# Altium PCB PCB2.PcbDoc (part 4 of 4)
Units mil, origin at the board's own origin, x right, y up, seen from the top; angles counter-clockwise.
Board outline 3980.79 x 2126 mil, 6 copper layers (Top Layer, Signal Layer 1, Signal Layer 2, Signal Layer 3, Signal Layer 4, Bottom Layer), stack 61.485 mil thick; 358 components, 190 nets, 1000 pads, 509 vias.
Unrouted connection lines stored in the file: 83.
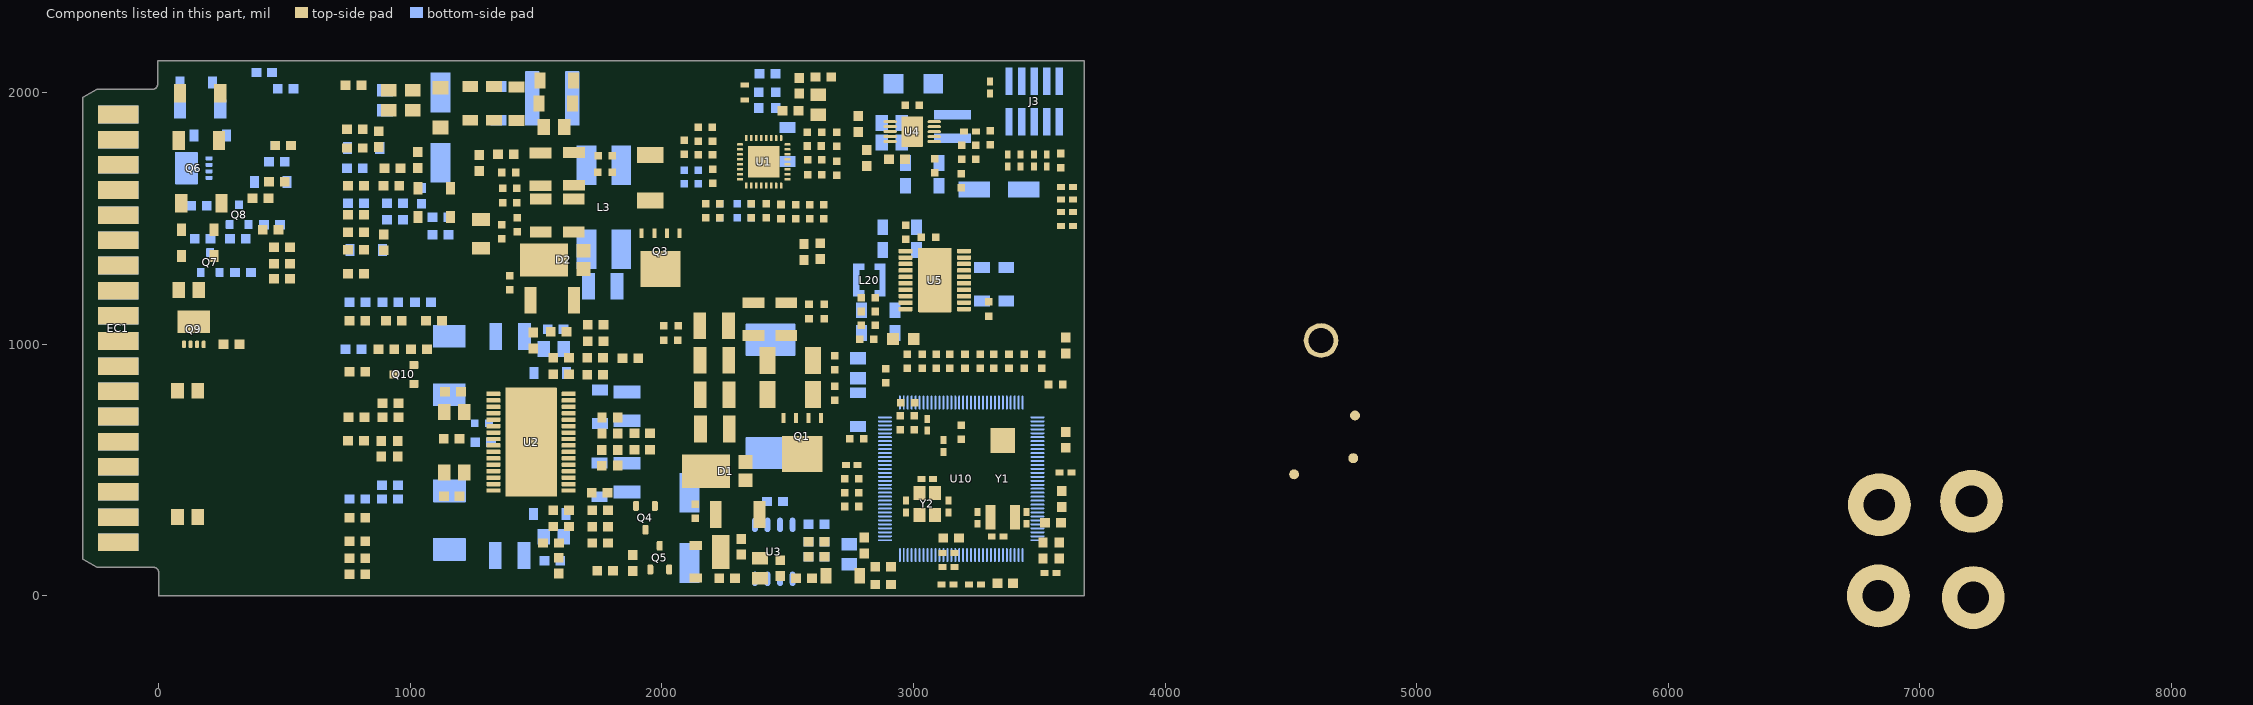
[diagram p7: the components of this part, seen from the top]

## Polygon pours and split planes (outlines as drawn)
Vin on Bottom Layer "BOTTOM_LAYER_VIN_P214" (solid, remove dead copper, pour order 214): 1575,2100.5 1575,1775 1765,1775 1770,1780 1770,2100.5
3V3 on Bottom Layer "BOTTOM_LAYER_3V3_P198" (solid, remove dead copper, pour order 198): 2740,1005 2740,1330 2815,1330 2815,1005
NetC68_1 on Bottom Layer "BOTTOM_LAYER_NETC68_1_P126" (solid, remove dead copper, pour order 126): 850,2100 850,1975 1350,1975 1455,1870 1515,1870 1515,2100
NetC68_1 on Bottom Layer "BOTTOM_LAYER_NETC68_1_P112" (solid, remove dead copper, pour order 112): 160,1624.51 160,2015 570,2015 570,1845 340,1845 315,1820 315,1625
DRLPOS on Bottom Layer "BOTTOM_LAYER_DRLPOS_P106" (solid, remove dead copper, pour order 106): -235,1750 -10,1750 21,1781 21,1864.71 159.71,1864.71 160,1865 160,1620 40,1620 -20,1680 -235,1680
LB1/LB2 on Bottom Layer "BOTTOM_LAYER_LB1/LB2_P100" (solid, remove dead copper, pour order 100): -245,1950 -55,1950 70,2075 115,2075 115,1880 -245,1880
NetC50_1 on Bottom Layer "BOTTOM_LAYER_NETC50_1_P038" (solid, remove dead copper, pour order 38): 1225.2,530.59 1225.2,370.59 1060.2,370.59 1060.2,530.59
NetC60_1 on Bottom Layer "BOTTOM_LAYER_NETC60_1_P028" (solid, remove dead copper, pour order 28): 1220.2,845.59 1220.2,690.59 1055.2,690.59 1055.2,845.59
Vin on Bottom Layer "BOTTOM_LAYER_VIN_P132" (solid, remove dead copper, pour order 132): 1770,1635 1770,1799.52 1460,1799.52 1460,1697.79 1463.03,1694.76 1645.24,1694.76 1660,1680 1660,1635
NetC16_1 on Bottom Layer "BOTTOM_LAYER_NETC16_1_P136" (solid, remove dead copper, pour order 136): 2596.85,1897.24 2468.31,1897.24 2466.85,1898.7 2466.85,1846.34 2475.94,1837.24 2596.85,1837.24
NetC30_1 on Bottom Layer "BOTTOM_LAYER_NETC30_1_P146" (solid, remove dead copper, pour order 146): 2115,1374.96 1885.04,1374.96 1884.99,1470 1780,1470 1780,1160 2115,1160
NetC18_2 on Bottom Layer "BOTTOM_LAYER_NETC18_2_P152" (solid, remove dead copper, pour order 152): 1420,1245 1640,1245 1640,1430 1420,1430
NetC30_2 on Bottom Layer "BOTTOM_LAYER_NETC30_2_P158" (solid, remove dead copper, pour order 158): 1650,1145 1650,1470 1780,1470 1780,1145
NetL7_2 on Bottom Layer "BOTTOM_LAYER_NETL7_2_P160" (solid, remove dead copper, pour order 160): 1365,1095 1025.55,1095 1025.55,950.55 1025,950 1365,950
LBHB+ on Bottom Layer "BOTTOM_LAYER_LBHB+_P162" (solid, remove dead copper, pour order 162): 1430,1100 1565,1100 1565,838.94 1430,838.94
NetL4_2 on Bottom Layer "BOTTOM_LAYER_NETL4_2_P164" (solid, remove dead copper, pour order 164): 1365,100 1050,100 1050,250 1365,250
DRLPOS+ on Bottom Layer "BOTTOM_LAYER_DRLPOS+_P166" (solid, remove dead copper, pour order 166): 1430,106.85 1430,370 1550,370 1550,105 1431.85,105
VBST on Bottom Layer "BOTTOM_LAYER_VBST_P170" (solid, remove dead copper, pour order 170): 2040,330 2040,599.69 2280,599.69 2280,330
NetD1_1 on Bottom Layer "BOTTOM_LAYER_NETD1_1_P176" (solid, remove dead copper, pour order 176): 2320.46,635 2685.94,635 2685.94,415.94 2685.91,415.96 2317.74,415.96 2317.74,632.28
Vin on Bottom Layer "BOTTOM_LAYER_VIN_P182" (solid, remove dead copper, pour order 182): 2530,1035 2530,1215 2310,1215 2310,1035
Vin on Bottom Layer "BOTTOM_LAYER_VIN_P184" (solid, remove dead copper, pour order 184): 2810,1925 2895,1925 2895,1770 2850,1770 2850,1870 2810,1870
NetC91_2 on Bottom Layer "BOTTOM_LAYER_NETC91_2_P186" (solid, remove dead copper, pour order 186): 3040,1890 3239.5,1890 3239.5,2094.5 3240,2095 3040,2095
5V on Bottom Layer "BOTTOM_LAYER_5V_P190" (solid, remove dead copper, pour order 190): 3066.22,1840.56 3066.22,1556.22 3065,1555 3065,1495 3305,1495 3305,1841.63 3067.3,1841.63
Vin on Top Layer "TOP_LAYER_VIN_P212" (solid, remove dead copper, pour order 212): 1575,2125.99 1575,1810 1460,1810 1460,1706.72 1471.96,1694.76 1645.24,1694.76 1680,1660 1770,1660 1770,2125.99
MCU_3V3D on Top Layer "TOP_LAYER_MCU_3V3D_P210" (solid, remove dead copper, pour order 210): 2735,15 2875,15 2875,150 2735,150
RST_N on Top Layer "TOP_LAYER_RST_N_P206" (solid, remove dead copper, pour order 206): 3245,33.19 3329.49,33.19 3350,53.7 3350,85 3340,95 3285,95 3245,55
NetC120_1 on Top Layer "TOP_LAYER_NETC120_1_P204" (solid, remove dead copper, pour order 204): 3230,305 3330,305 3330,210 3230,210
NetC121_1 on Top Layer "TOP_LAYER_NETC121_1_P202" (solid, remove dead copper, pour order 202): 3465.59,305 3410,305 3410,245 3465.59,245
5V on Top Layer "TOP_LAYER_5V_P200" (solid, remove dead copper, pour order 200): 3300,1340 3300,1285 3340,1285 3340,1340
5V on Top Layer "TOP_LAYER_5V_P196" (solid, remove dead copper, pour order 196): 2995,1325 2930,1325 2865,1390 2865,1420 2820,1420 2820,1337.6 2820,1285 2867.52,1285 2910,1285 2995,1285
HB_LED on Top Layer "TOP_LAYER_HB_LED_P128" (solid, remove dead copper, pour order 128): -240,1150 300,1150 300,1040 45,1040 5,1080 -240,1080
NetC68_1 on Top Layer "TOP_LAYER_NETC68_1_P124" (solid, remove dead copper, pour order 124): 775,2125 775,1975 1460,1975 1460,2125
NetC68_1 on Top Layer "TOP_LAYER_NETC68_1_P118" (solid, remove dead copper, pour order 118): 115,1525 390,1525 390,1850 565,1850 566.02,1851.02 566.02,1986.46 564.27,1988.21 390,1988.21 390,2125.99 115,2125.99
TI on Top Layer "TOP_LAYER_TI_P108" (solid, remove dead copper, pour order 108): -240,1550 -30,1550 30,1610 30.79,1609.21 160,1609.21 160,1412.5 37.5,1412.5 -30,1480 -235,1480
DRLPOS on Top Layer "TOP_LAYER_DRLPOS_P104" (solid, remove dead copper, pour order 104): -235,1750 -10,1750 21,1781 21,1870 115,1870 115,1680 -235,1680
LB1/LB2 on Top Layer "TOP_LAYER_LB1/LB2_P102" (solid, remove dead copper, pour order 102): -245,1950 -51.49,1950 73.95,2075.44 74.39,2075 115,2075 115,1880 -245,1880
NetC50_1 on Top Layer "TOP_LAYER_NETC50_1_P036" (solid, remove dead copper, pour order 36): 1165.2,375.59 1165.2,530.59 1060.2,530.59 1060.2,375.59
NetC60_1 on Top Layer "TOP_LAYER_NETC60_1_P030" (solid, remove dead copper, pour order 30): 1160.2,690.59 1160.2,845.59 1055.2,845.59 1055.2,690.59
NetC16_1 on Top Layer "TOP_LAYER_NETC16_1_P134" (solid, remove dead copper, pour order 134): 2666.85,1942.24 2586.42,1942.24 2572.87,1955.79 2511.85,1955.79 2511.85,1898.7 2486.85,1898.7 2486.85,1872.24 2666.85,1872.24
TI+ on Top Layer "TOP_LAYER_TI+_P140" (solid, remove dead copper, pour order 140): 1220,1460 1220,1720 1390,1720 1390,1530 1328.69,1530 1327.41,1531.28 1327.41,1450 1220,1450
NetQ3_1 on Top Layer "TOP_LAYER_NETQ3_1_P142" (solid, remove dead copper, pour order 142): 2100,1395 2100,1620 1885,1620 1885,1470 1935,1420 1935,1395
NetC30_1 on Top Layer "TOP_LAYER_NETC30_1_P144" (solid, remove dead copper, pour order 144): 2100,1395 2115,1395 2115,1155 1780,1155 1780,1470 2060.78,1470 2079.09,1451.69
NetC30_2 on Top Layer "TOP_LAYER_NETC30_2_P154" (solid, remove dead copper, pour order 154): 1645,1414.72 1645,1232.09 1610,1232.09 1610,1117.91 1757.91,1117.91 1760,1120 1760,1425 1651.31,1425 1646.31,1430
NetC18_2 on Top Layer "TOP_LAYER_NETC18_2_P156" (solid, remove dead copper, pour order 156): 1220,1245 1645,1245 1645,1410.14 1708.46,1410.14 1708.46,1498.46 1710,1500 1464.03,1500 1464.03,1475 1220,1475
VBST on Top Layer "TOP_LAYER_VBST_P168" (solid, remove dead copper, pour order 168): 2200,1150 2200,599.69 2280,599.69 2280,400 2175,400 2175,330 2040,330 2040,1150
NetC1_1 on Top Layer "TOP_LAYER_NETC1_1_P172" (solid, remove dead copper, pour order 172): 2090,330 2090,265 2278.4,265 2280,266.6 2280,400 2160,400
NetD1_1 on Top Layer "TOP_LAYER_NETD1_1_P174" (solid, remove dead copper, pour order 174): 2280,266.6 2280,594.54 2320.46,635 2685.94,635 2685.94,266.6 2448.4,266.6
NetQ1_1 on Top Layer "TOP_LAYER_NETQ1_1_P178" (solid, remove dead copper, pour order 178): 2523.94,680 2523.94,956.03 2560,992.09 2562.09,990 2650,990 2650,800 2710.62,800 2710,799.38 2710,680
Vin on Top Layer "TOP_LAYER_VIN_P180" (solid, remove dead copper, pour order 180): 2310,1215 2310,1135 2680,1135 2680,1215
NetC91_2 on Top Layer "TOP_LAYER_NETC91_2_P188" (solid, remove dead copper, pour order 188): 3066.22,1888.96 3025,1888.96 3025,1975 3170,1975 3170,1885 3070.18,1885
NetC68_1 on Signal Layer 4 "SIGNAL_LAYER_4_NETC68_1_P122" (solid, remove dead copper, pour order 122): 850,2100 850,2040 964.56,2040 965,2039.56 965,2100
NetC68_1 on Signal Layer 4 "SIGNAL_LAYER_4_NETC68_1_P120" (solid, remove dead copper, pour order 120): 450,1850 450,2045 455,2050 965,2050 965,1850
Vin on Signal Layer 2 "SIGNAL_LAYER_2_VIN_P216" (solid, remove dead copper, pour order 216): 1460,1085 1460,1685 1460,1910 2205,1910 2545,1570 2545,1085

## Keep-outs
Keep-Out Layer:
  text ".Layer_Name" at 293.21,-858.5 h60

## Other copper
Top Layer:
  rectangle net NetQ3_4: 2275,1440 2325,1470
  rectangle net NetC122_1: 2960,368.78 3050,476.81
  rectangle net NetC123_1: 3065,270 3155,345
  rectangle net MCU_3V3D: 3375,31.3 3445,70
  rectangle net 5V: 3180.69,1285 3340,1323.8
  rectangle net 3V3: 2740,1001.3 2810,1145
  rectangle net 5V: 2867.52,1285 2995,1323.8
  rectangle net NetL20_1: 2865,1220 2910,1275
  rectangle net NetQ9_4: 175,985 271.3,1010
  rectangle net GND: 570,25 720,2100
  region net NetQ3_4: 1935,1500 1880,1500 1880,1420 1935,1420
  rectangle net NetL8_1: 1190,695 1347.94,730.57
  rectangle net NetL5_1: 1190,490 1347.94,525.85
  rectangle net VBST: 1605,515 1710,551.44
  rectangle net VBST: 1608.52,670 1715,704.98
  rectangle net NetQ1_4: 2390,685 2490,725
  rectangle net DRLPOS+: 480,265 550,350
  rectangle net LBHB+: 485,760 550,860
  rectangle net NetEC1_15: -210,1180 105,1245
  rectangle net TI+: 135,1185 270,1245
  text ".Layer_Name" at 293.21,-858.5 h60
Signal Layer 2:
  rectangle net Vin: 2310,1165 2530,1215
Signal Layer 4:
  rectangle net NetQ3_4: 1880,1455 1935,1500
  rectangle net TI+: 1225,1500 1300,1565
  rectangle net DRLPOS+: 480,265 550,350
  rectangle net DRLPOS+: 1475,106.85 1550,190
  rectangle net LBHB+: 1430,865 1515,960
  rectangle net LBHB+: 470,760 550,860
  rectangle net TI+: 180,1185 270,1245
Bottom Layer:
  rectangle net MCU_3V3D: 2715,25 2865,150
  rectangle net 5V: 3150,1280 3400,1335
  rectangle net 5V: 2820,1337.6 2910,1575
  rectangle net NetL20_1: 2835,1185 2910,1325
  region net GND: 720,2100 570,2100 570,25 720,25
  rectangle net VBST: 1665,500 1915,550
  rectangle net VBST: 1667.2,664.47 1922.37,705
  text ".Layer_Name" at 293.21,-858.5 h60

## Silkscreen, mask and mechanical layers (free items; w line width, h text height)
Top Overlay:
  region: 4686.21,1129.99 4386.21,1129.99 4386.21,1029.99 4686.21,1029.99
  text "'.PRJ_Number'.PCB_Rev-" at 3851.21,1045.76 h108.27
  text ".Layer_Name" at 293.21,-858.5 h60
Bottom Overlay:
  text ".Layer_Name" at 293.21,-858.5 h60
Top Paste:
  text ".Layer_Name" at 293.21,-858.5 h60
Bottom Paste:
  text ".Layer_Name" at 293.21,-858.5 h60
Top Solder:
  text ".Layer_Name" at 293.21,-858.5 h60
  text ".Layer_Name" at 293.21,-858.5 h60
Bottom Solder:
  text ".Layer_Name" at 293.21,-858.5 h60
Drill Guide:
  text ".Layer_Name" at 293.21,-858.5 h60
M1 Board Outline:
  lines w10: -300.79,144.88 -300.79,1981.1 ; -245.67,2012.99 -23.62,2012.99 ; -3.93,2125.99 3680,2125.99 3680,-0.01 0.01,-0.01 ; 0,0 0.01,-0.01
  text ".Layer_Name" at 293.21,-858.5 h60
M2 Board Dimensions:
  rectangle: -283.79,-275.01 -158.79,-150.01
  rectangle: -158.79,-400.01 216.21,-275.01
  lines w7: -283.79,-275.01 716.21,-275.01 ; -158.79,-400.01 -158.79,-150.01 ; -33.79,-400.01 -33.79,-150.01 ; 216.21,-400.01 216.21,-150.01 ; 466.21,-400.01 466.21,-150.01 ; -283.79,-400.01 716.21,-400.01 716.21,-150.01 -283.79,-150.01 -283.79,-400.01
  text ".Layer_Name" at 293.21,-858.5 h60
M3 3D STEP Top:
  text ".Layer_Name" at 293.21,-858.5 h60
M4 3D STEP Bottom:
  text ".Layer_Name" at 293.21,-858.5 h60
M5 Assembly Top:
  lines w10: -575.79,-930.17 6024.21,-930.17 ; -575.79,-726.84 6026.21,-726.84 ; -575.79,-523.51 -575.79,-1133.51 3429.21,-1133.51 6026.21,-1133.51 6026.21,-523.51 -575.29,-523.51 -575.29,-1133.51 1000.21,-1133.51 ; 1889.21,-1133.51 1889.21,-523.51 ; 3156.21,-726.84 3156.21,-523.51 ; 3996.21,-726.84 3996.21,-523.51 ; 4618.21,-1140.01 4618.21,-937.17
  text "COMPONENTS MARKED 'DNP' SHOULD NOT BE POPULATED." at 869.71,-318.51 h60
  text "ASSEMBLY VARIANT:" at 869.21,-434.01 h60
  text ".VariantName" at 1905.21,-434.01 h60
  text "PCB VIEWED FROM TOP SIDE" at -512.29,-655.67 h60
  text "BOARD #:" at 1964.21,-655.67 h60
  text ".PRJ_Number" at 2509.71,-655.67 h60
  text "REV:" at 3354.21,-655.67 h60
  text ".PCB_Rev" at 3645.71,-655.67 h60
  text "SVN REV:" at 4192.21,-655.67 h60
  text ".VersionControl_RevNumber" at 4698.21,-655.67 h60
  text "TID #:" at 1964.21,-859.01 h60
  text ".TID" at 2509.71,-859.01 h60
  text "PLOT NAME =" at -512.29,-1064.34 h60
  text ".plot_File_Name" at 293.21,-1064.34 h60
  text "GENERATED    :" at 1966.21,-1064.34 h60
  text ".Print_Date" at 2835.71,-1064.34 h60
  text ".Print_Time" at 3564.71,-1064.34 h60
  text "TEXAS INSTRUMENTS" at 4829.21,-1064.34 h60
M6 Assembly Bottom:
  lines w10: -576.29,-727.34 6025.71,-727.34 ; -574.29,-930.67 6025.71,-930.67 ; 831.71,-1140.51 831.71,-937.67 ; 1453.71,-727.34 1453.71,-524.01 ; 2293.71,-727.34 2293.71,-524.01 ; 3560.71,-1134.01 3560.71,-524.01 ; 4449.71,-1134.01 6025.21,-1134.01 6025.21,-524.01 -576.29,-524.01 -576.29,-1134.01 2020.71,-1134.01 6025.71,-1134.01 6025.71,-524.01
  text "COMPONENTS MARKED 'DNP' SHOULD NOT BE POPULATED." at 5818.21,-318.01 h60
  text ".VariantName" at 4774.21,-434.01 h60
  text "ASSEMBLY VARIANT:" at 5813.21,-434.01 h60
  text ".VersionControl_RevNumber" at 751.71,-656.17 h60
  text "SVN REV:" at 1257.71,-656.17 h60
  text ".PCB_Rev" at 1804.21,-656.17 h60
  text "REV:" at 2095.71,-656.17 h60
  text ".PRJ_Number" at 2940.21,-656.17 h60
  text "BOARD #:" at 3485.71,-656.17 h60
  text "PCB VIEWED FROM BOTTOM SIDE" at 5962.21,-656.17 h60
  text ".TID" at 2940.21,-859.51 h60
  text "TID #:" at 3485.71,-859.51 h60
  text "TEXAS INSTRUMENTS" at 620.71,-1064.84 h60
  text ".Print_Time" at 1885.21,-1064.84 h60
  text ".Print_Date" at 2614.21,-1064.84 h60
  text "GENERATED    :" at 3483.71,-1064.84 h60
  text ".plot_File_Name" at 5156.71,-1064.84 h60
  text "PLOT NAME =" at 5962.21,-1064.84 h60
M9 Title Sheet:
  drawing of 57 lines, arcs and shapes, not listed
  text "1" at 456.05,8036.49 h70
  text "2" at 2951.71,8036.49 h70
  text "3" at 5441.06,8036.49 h70
  text "4" at 7947.72,8036.49 h70
  text "5" at 10446.71,8036.49 h70
  text "6" at 12951.71,8036.49 h70
  text "A" at -700.29,6893.49 h70
  text "A" at 14099.71,6893.49 h70
  text "B" at -700.29,4513.49 h70
  text "B" at 14099.71,4513.49 h70
  text "C" at -700.29,2138.49 h70
  text "C" at 14099.71,2138.49 h70
  text "PROJECT TITLE:" at 11059.71,277.49 h45
  text ".PRJ_Title" at 11109.71,144.17 h70
  text "DESIGNED FOR:" at 11059.71,-23.51 h45
  text ".PRJ_Customer" at 11109.71,-163.51 h70
  text "D" at -700.29,-231.51 h70
  text "D" at 14099.71,-231.51 h70
  text "FILE NAME:" at 11059.71,-323.51 h45
  text ".PCB_File_Name_No_Path" at 11109.71,-443.51 h70
  text "Texas Instruments (TI) and/or its licensors do not warrant the accuracy or completeness of this specification" at 6090.21,-605.35 h45
  text "ENGINEER:" at 11059.71,-613.51 h45
  text "LAYOUT BY:" at 12564.71,-613.51 h45
  text "or any information contained therein. TI and/or its licensors do not warrant that this design will meet" at 6045.23,-718.01 h45
  text ".PRJ_Engineer" at 11109.71,-768.5 h70
  text ".PCB_Layout" at 12615.21,-768.5 h70
  text "the specifications, will be suitable for your application or fit for any particular purpose, or will operate in" at 6045.23,-830.68 h45
  text ".Layer_Name" at 293.21,-858.5 h60
  text "ALTIUM DESIGNER VERSION:" at 12564.71,-923.51 h45
  text "an implementation. TI and/or its licensors do not warrant that the design is production worthy. You should" at 6045.23,-943.34 h45
  text "completely validate and test your design implementation to confirm the system functionality for your application." at 6090.21,-1056.01 h45
  text ".print_Scale" at 11109.71,-1056.83 h70
  text ".Application_BuildNumber" at 12615.21,-1056.83 h70
  text "1" at 456.05,-1263.51 h70
  text "2" at 2951.71,-1263.51 h70
  text "3" at 5441.06,-1263.51 h70
  text "4" at 7947.72,-1263.51 h70
  text "5" at 10446.71,-1263.51 h70
  text "6" at 12951.71,-1263.51 h70
M10 Fab Notes:
  drawing of 189 lines, arcs and shapes, not listed
  text "DESIGN INFORMATION" at 12098.23,6356.17 h60
  text "MIN. TRACK WIDTH:" at 11453.67,6224.04 h60
  text "8" at 12549.91,6224.04 h60
  text "MIL" at 12704.67,6224.04 h60
  text "MIN. CLEARANCE:" at 11453.67,6099.91 h60
  text "0.2" at 12489.91,6099.92 h60
  text "mm" at 12704.67,6099.91 h60
  text "MIN. VIA PAD SIZE:" at 11453.67,5975.79 h60
  text "24" at 12519.92,5975.79 h60
  text "MIL" at 12704.67,5975.79 h60
  text "0.05mm (2MIL)" at 12148.67,5845.89 h60
  text "MINIMUM ANNULAR RING" at 11124.44,5837.67 h60
  text "EXTERNAL" at 12856.67,5837.67 h60
  text "PER" at 11324.44,5727.54 h60
  text "IPC-D-275 CLASS 2 LEVEL C" at 11544.44,5727.54 h60
  text "MIL, HOLES" at 13032.67,5627.06 h60
  text "+/-" at 12640.21,5618.48 h60
  text "+/-" at 13494.21,5618.48 h60
  text "REGISTRATION TOLERANCES:" at 11124.44,5617.41 h60
  text "METAL" at 12324.21,5617.41 h60
  text "5" at 12900.41,5617.41 h60
  text "3" at 13733.41,5617.41 h60
  text "MIL" at 13849.67,5617.41 h60
  text "HOLE SIZE TOLERANCE (UNLESS OTHERWISE SPECIFIED):" at 11124.44,5519.1 h60
  text "+/-" at 13494.21,5516.22 h60
  text "3" at 13733.41,5515.16 h60
  text "MIL" at 13849.67,5515.16 h60
  text "MATERIAL:" at 11049.67,5377.51 h60
  text "FR-4 High Tg" at 12036.12,5248.99 h60
  text "X" at 11891.68,5241 h60
  text "FR-408" at 11470.67,5236.48 h60
  text "OTHER" at 12958.67,5236.48 h60
  text "62 MIL (1.6mm) +/-10%" at 11790.77,5093.45 h60
  text "X" at 11670.68,5091 h60
  text "THICKNESS:" at 11124.44,5085.23 h60
  text "OTHER" at 13075.67,5085.23 h60
  text "TOLERANCE:" at 11124.44,4946.91 h60
  text "X" at 11972.68,4946.91 h60
  text "ANSI IPC-6012 TYPE 3 CLASS 2" at 12150.69,4946.91 h60
  text "OTHER +/-" at 12150.67,4802.73 h60
  text "BOW & TWIST:" at 11124.44,4657.54 h60
  text "X" at 11972.68,4657.54 h60
  text "ANSI IPC-6012 TYPE 3 CLASS 2" at 12150.69,4657.54 h60
  text "OTHER +/-" at 12150.67,4510.84 h60
  text "DRILLING:" at 11049.67,4380.22 h60
  text "NC_DRILL FILES" at 12810.67,4275.03 h60
  text "REFERENCE:" at 11124.44,4271.1 h60
  text "X" at 11781.68,4271 h60
  text "AS SHOWN" at 11959.67,4271.1 h60
  text "X" at 12682.68,4271.1 h60
  text "OTHER" at 13108.67,4128.84 h60
  text "PTH COPPER THICKNESS:" at 11124.12,4125.31 h60
  text "X" at 12263.35,4125.31 h60
  text "20-30 um" at 12391.35,4125.31 h60
  text "BOARD FINISH:" at 11049.67,3977.72 h60
  text "SILKSCREEN:" at 11204.89,3867.59 h60
  text "X" at 12162.68,3867.59 h60
  text "TOP" at 12279.67,3867.59 h60
  text "X" at 12672.68,3867.59 h60
  text "BOTTOM" at 12790.67,3867.59 h60
  text "SILKSCREEN COLOR:" at 11204.89,3712.4 h60
  text "X" at 12161.68,3712.4 h60
  text "WHITE" at 12279.67,3712.4 h60
  text "OTHER" at 12790.67,3712.4 h60
  text "X" at 12292.68,3568.95 h60
  text "GREEN" at 12410.67,3568.95 h60
  text "OTHER" at 13028.67,3568.95 h60
  text "SOLDER RESIST COLOR:" at 11204.89,3562.09 h60
  text "X" at 12292.68,3414.7 h60
  text "MATTE" at 12410.67,3414.7 h60
  text "SEMI-GLOSS" at 13028.21,3414.06 h60
  text "IMMERSION GOLD (ENIG)" at 12110.67,3241.93 h60
  text "ENEPIG" at 13448.21,3234.71 h60
  text "SURFACE FINISH:" at 11049.67,3233.71 h60
  text "X" at 11932.68,3233.71 h60
  text "IMM. TIN/SILVER OR EQUIV" at 11379.21,3096.39 h60
  text "OTHER" at 12810.67,3092.46 h60
  text "ARRAY/PANEL:" at 11049.67,2937.08 h60
  text "CUT AND TRIM PER M1 BOARD OUTLINE" at 12110.67,2928.86 h60
  text "N.C. ROUTE" at 12110.67,2792.89 h60
  text "X" at 12798.68,2792.89 h60
  text "V. SCORE" at 12976.67,2792.89 h60
  text "CERTIFICATION:" at 11049.67,2663.76 h60
  text "MATERIALS AND WORKMANSHIP FOR ALL PCBS" at 11774.67,2663.76 h60
  text "TO MEET OR EXCEED THE REQUIREMENTS OF:" at 11774.67,2569.7 h60
  text "X" at 11412.18,2441.07 h60
  text "ANSI IPC-A-600F CLASS ->" at 11540.18,2441.07 h60
  text "X" at 13188.18,2441.07 h60
  text "2" at 13298.18,2441.07 h60
  text "1" at 12983.18,2439.58 h60
  text "3" at 13652.18,2439.58 h60
  text "X" at 12224.18,2293.39 h60
  text "RoHS" at 12352.18,2293.39 h60
  text "OTHER" at 12996.58,2293.39 h60
  text "PER ORDER" at 13393.63,2293.39 h60
  text "ALL BOARDS MUST MEET OR EXCEED UL94-V0 REQUIREMENTS." at 11077.21,2139.56 h60
  text "PCB MUST BEAR THE UL94V-0 UL REGISTERED MATERIAL ID NUMBER" at 11077.21,2023.5 h60
  text "ADDITIONAL REQUIREMENTS:" at 11049.67,1854.07 h60
  text "MICROSECTION:" at 11124.44,1746.95 h60
  text "YES" at 12030.18,1746.95 h60
  text "REQUIRED" at 12891.67,1602.61 h60
  text "BARE BOARD ELEC. TEST:" at 11124.44,1599.76 h60
  text "NONE" at 12430.18,1599.76 h60
  text "X" at 12773.68,1599.76 h60
  text "PER ORDER" at 13483.67,1599.76 h60
  text "XX MIL VIAS REQUIRE NON-CONDUCTIVE FILL AND PLANARIZE" at 11292.59,1394.81 h59
  text "XX MIL VIAS REQUIRE CONDUCTIVE FILL AND PLANARIZE" at 11300.59,1290.83 h60
  text "OUTER XX MIL TRACES REQUIRE 50 OHM SINGLE-ENDED IMPEDANCE" at 11299.61,1127.45 h58
  text "LAYER 2 & 3 (INNER LAYERS) XX MIL WIDE, XX MIL SPACE / TRACES REQUIRE 100 OHM DIFFERENTIAL IMPEDANCE" at 11291.61,891.74 h60
  text ".Layer_Name" at 293.21,-858.5 h60
M11 Gerber Information:
  lines w10: -575.79,-930.17 6024.21,-930.17 ; -575.79,-726.84 6026.21,-726.84 ; -575.79,-523.51 -575.79,-1133.51 3429.21,-1133.51 6026.21,-1133.51 6026.21,-523.51 -575.29,-523.51 -575.29,-1133.51 1000.21,-1133.51 ; 1889.21,-1133.51 1889.21,-523.51 ; 3156.21,-726.84 3156.21,-523.51 ; 3996.21,-726.84 3996.21,-523.51 ; 4618.21,-1140.01 4618.21,-937.17
  text "ALL ARTWORK VIEWED FROM TOP SIDE" at -512.29,-655.67 h60
  text "BOARD #:" at 1964.21,-655.67 h60
  text ".PRJ_Number" at 2509.71,-655.67 h60
  text "REV:" at 3354.21,-655.67 h60
  text ".PCB_Rev" at 3645.71,-655.67 h60
  text "SVN REV:" at 4192.21,-655.67 h60
  text ".VersionControl_RevNumber" at 4698.21,-655.67 h60
  text "LAYER NAME =" at -512.29,-858.5 h60
  text "TID #:" at 1964.21,-859.01 h60
  text ".TID" at 2509.71,-859.01 h60
  text "PLOT NAME =" at -512.29,-1064.34 h60
  text ".plot_File_Name" at 293.21,-1064.34 h60
  text "GENERATED    :" at 1966.21,-1064.34 h60
  text ".Print_Date" at 2835.71,-1064.34 h60
  text ".Print_Time" at 3564.71,-1064.34 h60
  text "TEXAS INSTRUMENTS" at 4829.21,-1064.34 h60
M12 Stackup:
  drawing of 715 lines, arcs and shapes, not listed
  text "Layer" at 4926.3,7732.49 h60
  text "Name" at 5336.21,7732.49 h60
  text "Material" at 6275.95,7732.49 h60
  text "Thickness" at 7135.72,7732.49 h60
  text "Constant" at 7785.56,7732.49 h60
  text "Board Layer Stack" at 8355.42,7732.49 h60
  text "Board Layer Stack" at 9475.1,7732.49 h60
  text "1" at 4926.3,7612.49 h60
  text "Top Overlay" at 5336.21,7612.49 h60
  text "2" at 4926.3,7492.49 h60
  text "Top Solder" at 5336.21,7492.49 h60
  text "Solder Resist" at 6275.95,7492.49 h60
  text "0.40mil" at 7135.72,7492.49 h60
  text "3.5" at 7785.56,7492.49 h60
  text "3" at 4926.3,7372.49 h60
  text "Top Layer" at 5336.21,7372.49 h60
  text "Copper" at 6275.95,7372.49 h60
  text "1.42mil" at 7135.72,7372.49 h60
  text "4" at 4926.3,7252.49 h60
  text "Dielectric 1" at 5336.21,7252.49 h60
  text "FR-4" at 6275.95,7252.49 h60
  text "12.00mil" at 7135.72,7252.49 h60
  text "4.2" at 7785.56,7252.49 h60
  text "5" at 4926.3,7132.49 h60
  text "Signal Layer 1" at 5336.21,7132.49 h60
  text "Copper" at 6275.95,7132.49 h60
  text "1.42mil" at 7135.72,7132.49 h60
  text "6" at 4926.3,7012.49 h60
  text "Dielectric 2" at 5336.21,7012.49 h60
  text "FR-4" at 6275.95,7012.49 h60
  text "8.50mil" at 7135.72,7012.49 h60
  text "4.2" at 7785.56,7012.49 h60
  text "7" at 4926.3,6892.49 h60
  text "Signal Layer 2" at 5336.21,6892.49 h60
  text "Copper" at 6275.95,6892.49 h60
  text "1.40mil" at 7135.72,6892.49 h60
  text "8" at 4926.3,6772.49 h60
  text "Dielectric 3" at 5336.21,6772.49 h60
  text "FR-4" at 6275.95,6772.49 h60
  text "12.00mil" at 7135.72,6772.49 h60
  text "4.2" at 7785.56,6772.49 h60
  text "9" at 4926.3,6652.49 h60
  text "Signal Layer 3" at 5336.21,6652.49 h60
  text "Copper" at 6275.95,6652.49 h60
  text "1.42mil" at 7135.72,6652.49 h60
  text "10" at 4926.3,6532.49 h60
  text "Dielectric 4" at 5336.21,6532.49 h60
  text "FR-4" at 6275.95,6532.49 h60
  text "8.50mil" at 7135.72,6532.49 h60
  text "4.2" at 7785.56,6532.49 h60
  text "11" at 4926.3,6412.49 h60
  text "Signal Layer 4" at 5336.21,6412.49 h60
  text "Copper" at 6275.95,6412.49 h60
  text "1.42mil" at 7135.72,6412.49 h60
  text "12" at 4926.3,6292.49 h60
  text "Dielectric 5" at 5336.21,6292.49 h60
  text "12.00mil" at 7135.72,6292.49 h60
  text "4.2" at 7785.56,6292.49 h60
  text "13" at 4926.3,6172.49 h60
  text "Bottom Layer" at 5336.21,6172.49 h60
  text "Copper" at 6275.95,6172.49 h60
  text "1.42mil" at 7135.72,6172.49 h60
  text "14" at 4926.3,6052.49 h60
  text "Bottom Solder" at 5336.21,6052.49 h60
  text "Solder Resist" at 6275.95,6052.49 h60
  text "0.40mil" at 7135.72,6052.49 h60
  text "3.5" at 7785.56,6052.49 h60
  text "15" at 4926.3,5932.49 h60
  text "Bottom Overlay" at 5336.21,5932.49 h60
  text ".Layer_Name" at 293.21,-858.5 h60
M13 Component Bodies Top:
  text ".Layer_Name" at 293.21,-858.5 h60
M14 Component Bodies Bottom:
  text ".Layer_Name" at 293.21,-858.5 h60
M15 Courtyards Top:
  text ".Layer_Name" at 293.21,-858.5 h60
M16 Courtyards Bottom:
  text ".Layer_Name" at 293.21,-858.5 h60
Drill Drawing:
  circle w10: c6276.76,4702.62 r22.14
  lines w10: 6254.62,4780.11 6298.9,4780.11 6298.9,4824.38 6254.62,4824.38 6254.62,4780.11 ; 6254.62,4879.73 6276.76,4890.8 6298.9,4879.73 6287.83,4901.87 6298.9,4924 6276.76,4912.94 6254.62,4924 6265.69,4901.87 6254.62,4879.73 ; 6254.62,5023.63 6298.9,5023.63 6276.76,4979.35 6254.62,5023.63 ; 6254.62,5090.04 6265.69,5090.04 6265.69,5078.97 6287.83,5078.97 6287.83,5090.04 6298.9,5090.04 6298.9,5112.18 6287.83,5112.18 6287.83,5123.25 6265.69,5123.25 6265.69,5112.18 6254.62,5112.18 6254.62,5090.04 ; 6254.62,5189.66 6265.69,5189.66 6276.76,5178.6 6287.83,5189.66 6298.9,5189.66 6287.83,5200.73 6298.9,5211.8 6287.83,5211.8 6276.76,5222.87 6265.69,5211.8 6254.62,5211.8 6265.69,5200.73 6254.62,5189.66 ; 6254.62,5278.22 6254.62,5289.29 6265.69,5300.36 6254.62,5311.43 6254.62,5322.49 6265.69,5322.49 6276.76,5311.43 6287.83,5322.49 6298.9,5322.49 6298.9,5311.43 6287.83,5300.36 6298.9,5289.29 6298.9,5278.22 6287.83,5278.22 6276.76,5289.29 6265.69,5278.22 6254.62,5278.22
  lines w12: 6213.86,4650.6 9326.8,4650.6 ; 6213.86,5347.95 9326.8,5347.95 ; 6529.5,4550.97 6529.5,5447.58 ; 6846.68,4550.97 6846.68,5447.58 ; 7468.42,4550.97 7468.42,5447.58 ; 7712.74,4550.97 7712.74,5447.58 ; 8073.08,4550.97 8073.08,5447.58 ; 8782.6,4550.97 8782.6,5447.58 ; 6213.86,4550.97 9326.8,4550.97 9326.8,5447.58 6213.86,5447.58 6213.86,4550.97
  text "Symbol" at 6273.64,5377.84 h72
  text "Quantity" at 6559.38,5377.84 h72
  text "Finished Hole Size" at 6876.57,5377.84 h72
  text "Plated" at 7498.31,5377.84 h72
  text "Hole Type" at 7742.63,5377.84 h72
  text "Drill Layer Pair" at 8102.97,5377.84 h72
  text "Hole Tolerance" at 8812.48,5377.84 h72
  text "75" at 6559.38,5278.22 h60
  text "7.87mil (0.200mm)" at 6876.57,5278.22 h60
  text "PTH" at 7498.31,5278.22 h60
  text "Round" at 7742.63,5278.22 h60
  text "Top Layer - Bottom Layer" at 8102.97,5278.22 h60
  text "128" at 6559.38,5178.6 h60
  text "8.00mil (0.203mm)" at 6876.57,5178.6 h60
  text "PTH" at 7498.31,5178.6 h60
  text "Round" at 7742.63,5178.6 h60
  text "Top Layer - Bottom Layer" at 8102.97,5178.6 h60
  text "1" at 6559.38,5078.97 h60
  text "8.00mil (0.203mm)" at 6876.57,5078.97 h60
  text "PTH" at 7498.31,5078.97 h60
  text "Round" at 7742.63,5078.97 h60
  text "Top Layer - Bottom Layer" at 8102.97,5078.97 h60
  text "+16.00mil" at 8812.48,5078.97 h60
  text "287" at 6559.38,4979.35 h60
  text "10.00mil (0.254mm)" at 6876.57,4979.35 h60
  text "PTH" at 7498.31,4979.35 h60
  text "Round" at 7742.63,4979.35 h60
  text "Top Layer - Bottom Layer" at 8102.97,4979.35 h60
  text "18" at 6559.38,4879.73 h60
  text "28.00mil (0.711mm)" at 6876.57,4879.73 h60
  text "PTH" at 7498.31,4879.73 h60
  text "Round" at 7742.63,4879.73 h60
  text "Top Layer - Bottom Layer" at 8102.97,4879.73 h60
  text "1" at 6559.38,4780.11 h60
  text "98.43mil (2.500mm)" at 6876.57,4780.11 h60
  text "PTH" at 7498.31,4780.11 h60
  text "Round" at 7742.63,4780.11 h60
  text "Top Layer - Bottom Layer" at 8102.97,4780.11 h60
  text "4" at 6559.38,4680.48 h60
  text "125.98mil (3.200mm)" at 6876.57,4680.48 h60
  text "PTH" at 7498.31,4680.48 h60
  text "Round" at 7742.63,4680.48 h60
  text "Top Layer - Bottom Layer" at 8102.97,4680.48 h60
  text "514 Total" at 6559.38,4580.86 h60
  text ".Layer_Name" at 293.21,-858.5 h60
Mechanical 17:
  lines w10: 21,0 21,2126
  text ".Layer_Name" at 293.21,-858.5 h60
Mechanical 18:
  text ".Layer_Name" at 293.21,-858.5 h60
Mechanical 19:
  text ".Layer_Name" at 293.21,-858.5 h60

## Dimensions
-283.79,-400.01 to 716.21,-400.01 on M2 Board Dimensions
3680,-0.01 to 0.01,-0.01 on M2 Board Dimensions
3680,2125.99 to 3680,-0.01 on M2 Board Dimensions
